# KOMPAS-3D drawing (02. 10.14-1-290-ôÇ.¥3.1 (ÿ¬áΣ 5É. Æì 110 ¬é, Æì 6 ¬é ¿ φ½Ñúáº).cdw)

Views: Вид 2
Referenced files in C:\Program Files\ASCON\KOMPAS-3D V9\Libs\: ELUSTR.LFR
Referenced files in D:\Работа\Информация\: Библиотека РЗА.lfr|02 - Вторичные цепи|Клеммы, перемычки, соединения|02-Клемма измерительная, Библиотека РЗА.lfr, Библиотека РЗА.lfr|Эл. соединение (точка), Библиотека РЗА.lfr|02 - Вторичные цепи|Клеммы, перемычки, соединения|01-Клемма, Библиотека РЗА.lfr|02 - Вторичные цепи|Контакты|Контакт 01, Библиотека РЗА.lfr|02 - Вторичные цепи|Катушки реле|Катушка реле 01, Библиотека РЗА.lfr|Стрелка
Referenced files in int C:\Program Files\ASCON\KOMPAS-3D V9\Libs\ELUSTR.LFR|Для меня|X:\Библиотека для РЗА\элементы\: электрич. соединение.frw
Referenced files in Для меня|X:\Библиотека для РЗА\элементы\: электрич. соединение.frw
Referenced files in C:\Program Files\ASCON\KOMPAS-3D V10\Libs\: 12.lfr|Резистор_1, 12.lfr, 777.lfr|клемма1, 777.lfr
Referenced files in D:\: Библиотека РЗА.lfr|02 - Вторичные цепи|Контакты|Кнопка, Библиотека РЗА.lfr
Referenced files in C:\Users\РЗА Елена\Desktop\: Библиотека РЗА.lfr|02 - Вторичные цепи|Контакты|Кнопка н.з., Библиотека РЗА.lfr, Библиотека РЗА.lfr|02 - Вторичные цепи|Лампы, светодиоды|Лампа
Referenced files in Z:\Информация\: Библиотека РЗА.lfr
Referenced files: входные цепи.cdw
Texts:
  Стрекаловский
  Текст на чертеже
  Размерные надписи
  Шероховатость
  Линия-выноска #1
  Линия-выноска #2
  Линия-выноска #3
  Отклонения формы и база
  Заголовок таблицы
  Ячейка таблицы
  Стрелка вида
  Обозначение изменения
  Фигурная скобка
  Номер узла
  Марка координационной оси
  VRCB
  Выносная надпись
  Обозначение узла
  Марка/позиционное обозначение с линией-выноской
  Марка/позиционное обозначение на линии
  Марка/позиционное обозначение без линии-выноски
  int C:\Program Files\ASCON\KOMPAS-3D V9\Libs\ELUSTR.LFR|Для меня|стрелка обрыва цепи
  Для меня|стрелка обрыва цепи
  int C:\Program Files\ASCON\KOMPAS-3D V9\Libs\ELUSTR.LFR|01|электрич
  02 - Вторичные цепи|Клеммы, перемычки, соединения|02-Клемма измерительная
  Эл. соединение (точка)
  02 - Вторичные цепи|Клеммы, перемычки, соединения|01-Клемма
  Резистор_1
  02 - Вторичные цепи|Контакты|Кнопка
  int C:\Program Files\ASCON\KOMPAS-3D V9\Libs\ELUSTR.LFR|Элементы|Диод
  Элементы|Диод
  02 - Вторичные цепи|Контакты|Контакт 01
  02 - Вторичные цепи|Катушки реле|Катушка реле 01
  Стрелка
  02 - Вторичные цепи|Контакты|Кнопка н.з.
  02 - Вторичные цепи|Лампы, светодиоды|Лампа
  клемма1
  int C:\Program Files\ASCON\KOMPAS-3D V9\Libs\ELUSTR.LFR|01|катушка реле 1
  Библиотека РЗА.lfr
  цепи
  Подпись в квадратике
  ссылки
  Без имени
  табл
  CONTINUOUS0
  ГОСТ2.730-73
  Стили документа
  ГОСТ2.732-68
  Лит-Масса-Масштаб
  Материал-Предприятие
  Additional DXF text style 0
  Normal
  Обычный
  Термин
  Список определений
  Адрес
  Цитаты
  Форматированный
  Courier New
  Z-конец формы
  Z-начало формы
  Title Specification
  Body Specification ( left align )
  Body Specificaton ( centered )
  Body Text
  heading 1
  Знак Знак Знак Знак Знак Знак
  Verdana
  heading 8
  heading 3
  heading 6
  heading 7
  ТекстШаг1
  Simplex
  Txt
  txt
  russ
  ООббыыччнныыйй
  ТТееррммиинн
  ССппииссоокк ооппррееддееллеенниийй
  ААддрреесс
  ЦЦииттааттыы
  ФФооррммааттиирроовваанннныыйй
  Z-ккооннеецц ффооррммыы
  Z-ннааччааллоо ффооррммыы
  Абзац Знак
  heading 2
  heading 4
  heading 5
  heading 9
  MS Sans Serif
  Тексты. 3,2
  ЗОНА_привяз
  Body Text 3
  Title
  Маркировка
  Аппараты
  подписи
  текст переноса
  клеммы, контакты
  тексты табл
  AGOpus
  footer
  маркировка
  Денис
  Клеммник текст
  rustxt
  Table Contents
  Table Heading
  Tahoma
  Definition Term
  Definition List
  Address
  Blockquote
  Preformatted
  z-Bottom of Form
  z-Top of Form
  Ссылки
  Состав чартежа
  Пояснения
  header
  Текст 3,5
  ГОСТ_МНЕ
  ESK - Обозначение
  ячейка табл.
  Body Text Indent 3
  Основной текст с отступом 3
  TXT
  GOST 2.304 type A
  ISOCP
  style2
  Шрифт 2.5
  Заголовки
  HeliosLight
  Pa3
  Pa1
  RUSTXT
  romanc
  CM12
  romans
  NormalParagraphStyle
  FR5
  Subtitle
  Три с половиной
  eskd1
  Pa15
  Pa18
  терминал
  CNBNDG+TimesNewRoman
  gif
  Пояснения 2
  текст табл
  ISOCPEUR
  CC С?т?и?л?ь? П?о? ц?е?н?т?р?у?
  Вопрос
  Блок
  Цепи напряжения
  Цепи сигнализации
  Контроль
  изоляции цепей
  напряжения
  Цепи
  "звезды"
  Измерение
  фазных и
  линейных
  напряжений
  "разомкнутого
  треугольника"
  PA1
  SB1
  Шинки
  сигнализации
  Аварийное
  отключение
  автоматов
  оперативных
  цепей и
  питания
  устройств
  снижение
  давления элегаза
  В 110 кВ 1Т
  Снижение
  В 110 кВ 2Т
  Сброс
  ТН 1 с.ш. 110 кВ
  -EС1.1
  +EС1.1
  +EС1.2
  -EС1.2
  Вводные
  рубильники
  шинок
  управления
  Секционирование
  Цепи питания
  SF1
  SF12
  SF13
  SF4
  SF15
  SF6
  SF7
  SF8
  SF9
  SF10
  Основная
  защита 1Т
  Газовая
  защита 2Т
  Резервная
  Управление
  (ЭМВ, ЭМО1)
  (ЭМО2)
  АРКТ 1Т
  Автоматика
  охлаждения 1Т
  Блокирующий
  комплект
  ВЛ 110 кВ
  Питание приемо-
  передатчика
  Авант Р400
  Резерв
  SF11
  SF2
  SF3
  SF14
  SF5
  SF16
  SF17
  SF18
  SF19
  SF20
  АРКТ 2Т
  охлаждения 2Т
  Питание
  измерительных
  приборов
  Питание реле-
  повторителей
  элегаза
  Автоматы
  Дистанционные
  расцепители
  Цепи питания измерительных приборов
  PV1
  PА1
  вольтметра
  амперметра
  ТН 1 с.ш. 6 кВ
  ТН 2 с.ш. 6 кВ
  PV2
  Оперативные цепи реле-повторителей давления элегаза
  Выходные цепи реле-повторителей давления элегаза
  KL1
  KL3
  KL4
  KL5
  KL6
  KL2
  Сигнализация
  снижения
  В 110 кВ 1Т в
  защиту 1Т
  В 110 кВ 2Т в
  защиту 2Т
  силового
  оборудования
  в центральную
  сигнализацию
  в теле-
  Цепи освещения шкафа
  EL1
  +EН
  SN1
  Монтажная единица 01
  Монтажная единица 02
  SN2
  Монтажная единица 03
  Монтажная единица 04
  HL1
  HL2
  VD1
  VD2
  HL3
  VD3
  HL4
  VD4
  HL5
  VD5
  VD6
  HL6
  SB2
  -EН
  + EН
  Монтажная единица 00
  Перечень аппаратуры
  осн 2
  Толщина 0,5
  Реле R15 4C/0-1114-23-1220 c контактной колодкой GZ14U
  фирма Relpol
  KQS1-KQS14
  Реле промежуточное РП252УХЛ4, 110В
  присоединение заднее
  KQS15-KQS42
  Реле промежуточное РП23УХЛ4, 110В
  Резистор ПЭ2-25, 150 Ом
  KH1...КН3
  Реле указательное РЭУ11-20-5-40 У3, 220В
  Разраб.
  Алдошина
  ПС 110/10 "Слободка"
  Н.контр.
  Борисов
  Реконструкция ПС 110 кВ Опорная
  (замена трансформаторов 16МВА на 40МВА)
  Защита и автоматика управления
  обходным выключателем 110 кВ.
  Схема электрическая принципиальная.
  Галкин
  Лобачёв
  ТН-110 кВ.
  Схема электрическая принципиальная
  ТН 110 кВ.
  Перечень элементов
  УА.22-
  Шкаф 5Р. ТН 110 кВ, ТН 6 кВ и элегаз.
Dimensions and other numbers on the sheet: 10/14-1-290-УА.Э3.1; 7; 01|электрич; 01|катушка реле 1; 3,2 (надписи); 2,5 (контакты, клеммы); 6; 2,5_3; 3,2_; 3,2_зона не привяз; 1,8; 2.5 курсив; 2,5; 5_заголовок; 2,5_01; 2,3_; 2.5; 3,5_01; 3,5_tabl; 3,2; 3.5; 2,5 грязносинь; 3,5; 5; 3,2 элементы; 3,2 линия; 3,2 таблица; 3.2 маркировка; 2.5_Э5_надписи; 2.5_Э5_ссылки; 2.5_кабель; 3.2; 2.5 надписи; 3,2 (Зоны); 3.2 (текст); 5 ШРИФТ; 5,0_белый_подчёркнутый; 3.2 фиол; 3 и 5; 1 с.ш. 110 кВ; 2; 1; 3; 4; 2 с.ш. 6 кВ; 1 с.ш. 6 кВ; 13; 8; 9; 17; 25; 33; 44; 34; 45; 35; 46; 36; 47; 37; 49; 38; 51; 39; 52; 40; 53; 41; 54; 42; 55; 48; 1-402; 2-502; 50; 57; 68; 58; 69; 59; 70; 60; 71; 61; 73; 62; 75; 63; 76; 64; 77; 65; 78; 66; 79; 72; 2-402; 1-502; 74; 11; 12; 10; 15; 16; 21; 22; 27; 28; 29; 30; 31; 32; 43; 18; 19; 24; 95; 96; 0; 14; 3,4; 7,8; 1,2; 11.12; 05.10; 10/14-1-022-УА-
